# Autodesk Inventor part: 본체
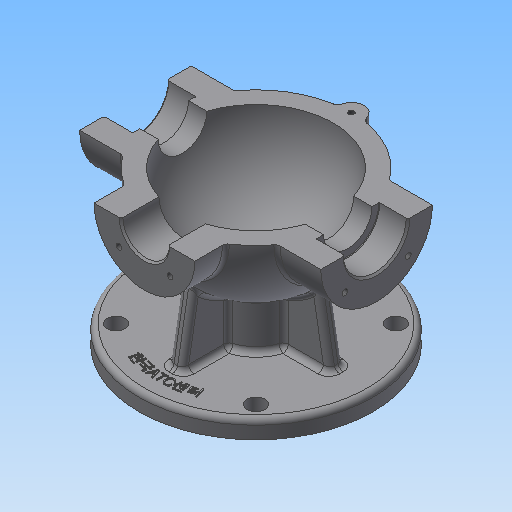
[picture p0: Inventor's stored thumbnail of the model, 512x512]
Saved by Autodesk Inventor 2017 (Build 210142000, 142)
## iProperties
Created: 2015-12
Part Number: 본체
Material: 일반
Document SubType Name: Modeling
Designer: mduedu
Density: 1 g/cm^3
Appearance: 기본값
Mass: 356.593 g
Surface Area: 788.536 cm^2
Volume: 356.593 cm^3
Author: mduedu
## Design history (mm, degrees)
sketch "스케치1"
  geometry: L1 (-53, 0)-(53, 0); A1 r 53 centre (0, 0) between (53, 0) and (-53, 0); 2 further points
  constraints: 2 coincident, 2 end point, 2 point on circle, 1 centre point, 1 horizontal, 1 midpoint
  dimensions: "d0" = 53 radius of A1
revolve "회전1" sketch "스케치1" stored, may be unused: angle "d2" = 90 deg
feature "쉘1" dims "d11" = 10
node "작업 평면1"
sketch "스케치2"
  geometry: C1 r 31 at (0, 0); 1 further point
  constraints: 1 centre point, 1 coincident
  dimensions: "d4" = 62 diameter of C1
extrude "돌출1" join sketch "스케치2" stored distance "d5" = 10; taper "d6" = 0 deg
node "작업 평면2"
sketch "스케치3"
  geometry: C1 r 28 at (0, 0); 1 further point
  constraints: 1 centre point, 1 coincident
  dimensions: "d8" = 56 diameter of C1
extrude "돌출2" join sketch "스케치3" stored distance "d9" = 10; taper "d10" = 0 deg
hole "구멍1" diameter "d14" = 35; stored, may be unused: countersink angle "d18" = 90 deg, drill point angle "d20" = 0 deg; dims "d12" = 10, "d13" = 10, "d15" = 6, "d16" = 4, "d17" = 2, "d19" = 16
hole "구멍2" diameter "d23" = 27; stored, may be unused: countersink angle "d27" = 90 deg, drill point angle "d29" = 0 deg; dims "d21" = 10, "d22" = 10, "d24" = 6, "d25" = 4, "d26" = 2, "d28" = 16
fillet "모깎기1" dims "d30" = 0.3
hole "구멍3" diameter "d33" = 26; stored, may be unused: countersink angle "d37" = 90 deg, drill point angle "d39" = 0 deg; dims "d31" = 10, "d32" = 10, "d34" = 6, "d35" = 4, "d36" = 2, "d38" = 16
chamfer "모따기1" distance "d40" = 1; stored, may be unused: second distance "d41" = 2, angle "d42" = 45 deg
sketch "스케치4"
  geometry: L1 (0, 0)-(0, -25); L2 (0, 0)-(-17.678, -17.678); A1 r 25 centre (0, 0) between (-17.678, -17.678) and (0, -25); 1 further point
  constraints: 4 end point, 2 point on circle, 1 centre point, 1 coincident, 1 vertical
  dimensions: "d43" = 50 diameter of A1; "d47" = 45 deg angle of L1 L2
hole "구멍4" sketch "스케치4" at (-17.678, -17.678) diameter "d49" = 3.242; stored, may be unused: countersink angle "d53" = 90 deg, drill point angle "d55" = 118 deg; dims "d50" = 11, "d51" = 4, "d52" = 2, "d54" = 13
sketch "스케치5"
  geometry: L1 (0, 0)-(0, -20); L2 (0, 0)-(-14.142, -14.142); A1 r 20 centre (0, 0) between (0, -20) and (-14.142, -14.142); 2 further points
  constraints: 4 end point, 2 coincident, 2 point on circle, 1 centre point, 1 vertical
  dimensions: "d59" = 40 diameter of A1; "d65" = 45 deg angle of L1 L2
hole "구멍5" sketch "스케치5" at (-14.142, -14.142) diameter "d67" = 3.242; stored, may be unused: countersink angle "d71" = 90 deg, drill point angle "d73" = 118 deg; dims "d68" = 8, "d69" = 4, "d70" = 2, "d72" = 10
node "작업 평면3"
sketch "스케치6"
  geometry: C1 r 65 at (0, 0); 1 further point
  constraints: 1 centre point, 1 coincident
  dimensions: "d78" = 130 diameter of C1
extrude "돌출3" join sketch "스케치6" distance "d80" = 10; taper "d81" = 0 deg
sketch "스케치7"
  geometry: C1 r 20 at (0, 0); 1 further point
  constraints: 1 centre point, 1 coincident
  dimensions: "d82" = 40 diameter of C1
extrude "돌출4" join sketch "스케치7" stored distance "d84" = 10; taper "d85" = 0 deg
sketch "스케치8"
  geometry: 2 further points
  constraints: 1 coincident
hole "구멍6" sketch "스케치8" at (0, 0) diameter "d86" = 20; stored, may be unused: countersink angle "d90" = 90 deg, drill point angle "d92" = 118 deg; dims "d87" = 7, "d88" = 40, "d89" = 5, "d91" = 10
fillet "모깎기2" dims "d93" = 0.3
sketch "스케치9"
  geometry: L1 (65, -75)-(-65, -75) reference; L2 (-45, -75)-(-38.245, -36.692); A1 r 53 centre (0, 0) between (42.988, 31) and (42.988, -31) reference; 1 further point
  constraints: 2 end point, 1 point on circle, 1 point on line
  dimensions: "d94" = 45 horizontal distance of L2.start point (0, 0); "d95" = 80 deg angle of L2 L1
feature "리브1" sketch "스케치9" dims "d96" = 1, "d97" = 8, "d98" = 0, "d99" = 0, "d100" = 1, "d101" = 1
sketch "스케치10"
  geometry: L1 (0, 0)-(0, -55); L2 (0, 0)-(-38.891, -38.891); A1 r 55 centre (0, 0) between (0, -55) and (-38.891, -38.891); 2 further points
  constraints: 4 end point, 2 coincident, 2 point on circle, 1 centre point, 1 vertical
  dimensions: "d105" = 110 diameter of A1; "d107" = 45 deg angle of L1 L2
hole "구멍7" sketch "스케치10" at (-38.891, -38.891) diameter "d109" = 10; stored, may be unused: countersink angle "d113" = 90 deg, drill point angle "d115" = 118 deg; dims "d110" = 7, "d111" = 40, "d112" = 5, "d114" = 10
fillet "모깎기3" dims "d120" = 3
fillet "모깎기4" dims "d121" = 3, "d122" = 3
fillet "모깎기5" dims "d123" = 3
fillet "모깎기6" dims "d124" = 3
sketch "스케치11"
  geometry: C1 r 5 at (-38.891, 38.891) reference; C2 r 5 at (38.891, 38.891) reference; C3 r 5 at (38.891, -38.891) reference; C4 r 5 at (-38.891, -38.891) reference; C5 r 20 at (0, 0) reference; C6 r 65 at (0, 0) reference; 1 further point
  constraints: 3 other
feature "엠보싱1" sketch "스케치11" dims "d125" = 0.5, "d126" = 0
sketch "스케치12"
  geometry: L1 (0, 100)-(0, -100); L2 (0, 100)-(100, 100); L3 (100, 100)-(100, -100); L4 (100, -100)-(0, -100); 2 further points
  constraints: 8 end point, 3 perpendicular, 1 coincident, 1 midpoint, 1 vertical
  dimensions: "d127" = 200 distance of L2.end L3.end; "d129" = 100 distance between parallel lines of L1 L3
extrude "돌출5" cut sketch "스케치12" stored distance "d130" = 10; taper "d131" = 0 deg
sketch "스케치13"
  geometry: C1 r 7 at (0, 53); A1 r 53 centre (0, 0) between (42.113, 32.179) and (-42.113, 32.179) reference; 1 further point
  constraints: 1 centre point, 1 point on circle
  dimensions: "d132" = 14 diameter of C1
extrude "돌출6" join sketch "스케치13" distance "d134" = 15; taper "d135" = 0 deg
hole "구멍8" diameter "d139" = 3.242; stored, may be unused: countersink angle "d143" = 90 deg, drill point angle "d145" = 118 deg; dims "d140" = 8, "d141" = 4, "d142" = 2, "d144" = 10, "d148" = 10, "d149" = 10
fillet "모깎기7" dims "d146" = 3
fillet "모깎기8" dims "d147" = 3
node "솔리드1"
mirror "대칭1"
mirror "대칭2"
pattern_circular "원형 패턴1" dims angle "d57" = 360 deg
mirror "대칭3"
pattern_circular "원형 패턴2" dims angle "d75" = 360 deg
pattern_circular "원형 패턴3" dims angle "d103" = 360 deg
pattern_circular "원형 패턴4" dims angle "d118" = 360 deg
node "투영된 루프1"
other parameters: "d3" = 67, "d7" = 62, "d77" = -85
